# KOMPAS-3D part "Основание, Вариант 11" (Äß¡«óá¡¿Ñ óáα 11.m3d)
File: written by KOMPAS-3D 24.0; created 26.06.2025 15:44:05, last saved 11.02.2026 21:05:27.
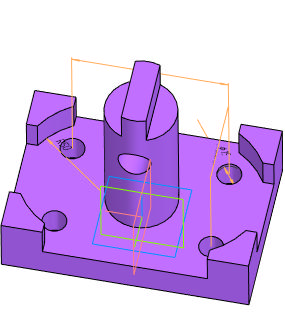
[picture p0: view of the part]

Document properties: Автор: Helen; Полное имя файла: C:\Для ноута\Инженерная графика\ППЭ 2025-2026\Варианты 1-38\Вариант 11 СБ\Вар 11 СБ\Основание вар 11.m3d

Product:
- Part/product: Основание  | designation Вариант 11
    Масса: 3.586869

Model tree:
1. Эскиз:1
2. Элемент выдавливания:1
     Расстояние 1 = 20
3. Эскиз:2  (with: Грань.Элемент выдавливания:1, Ребро.Элемент выдавливания:1)
4. Элемент выдавливания:2
     Расстояние 1 = 20
5. Зеркальный массив:1
6. Экземпляр ( 1 )
7. Экземпляр ( 2 )  (with: Элемент выдавливания:2)
8. Зеркальный массив:2  (with: Экземпляр ( 1 ), Экземпляр ( 2 ), Зеркальный массив:1, Элемент выдавливания:2)
9. Эскиз:3  (with: Грань.Элемент выдавливания:1, Ребро.Элемент выдавливания:1)
10. Элемент выдавливания:3
11. Зеркальный массив:3  (with: Экземпляр ( 1 ), Экземпляр ( 2 ), Элемент выдавливания:3)
12. Зеркальный массив:4  (with: Экземпляр ( 1 ), Экземпляр ( 2 ), Зеркальный массив:3, Элемент выдавливания:3)
13. Эскиз:6  (with: Грань.Элемент выдавливания:1)
14. Элемент выдавливания:6
     Расстояние 1 = 90
15. Эскиз:7  (with: Грань.Элемент выдавливания:6, Ребро.Элемент выдавливания:6)
16. Элемент выдавливания:7
     Расстояние 1 = 20
17. Эскиз:8
18. Элемент выдавливания:8
     Расстояние 1 = 50
19. Радиальный размер:1  (with: Ребро.Элемент выдавливания:2)
     Значение = 50
20. Линейный размер:1  (labels: Ребро.Элемент выдавливания:3.Экземпляр ( 1 ); Грань.Элемент выдавливания:3.Экземпляр ( 2 ))
     Значение = 53.6231
21. Линейный размер:2  (with: Ребро.Элемент выдавливания:3)  (labels: Грань.Элемент выдавливания:3.Экземпляр ( 1 ))
     Значение = 94.9951
22. Диаметральный размер:1  (labels: Грань.Элемент выдавливания:3.Экземпляр ( 1 ))
     Значение = 15

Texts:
  Вариант 11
